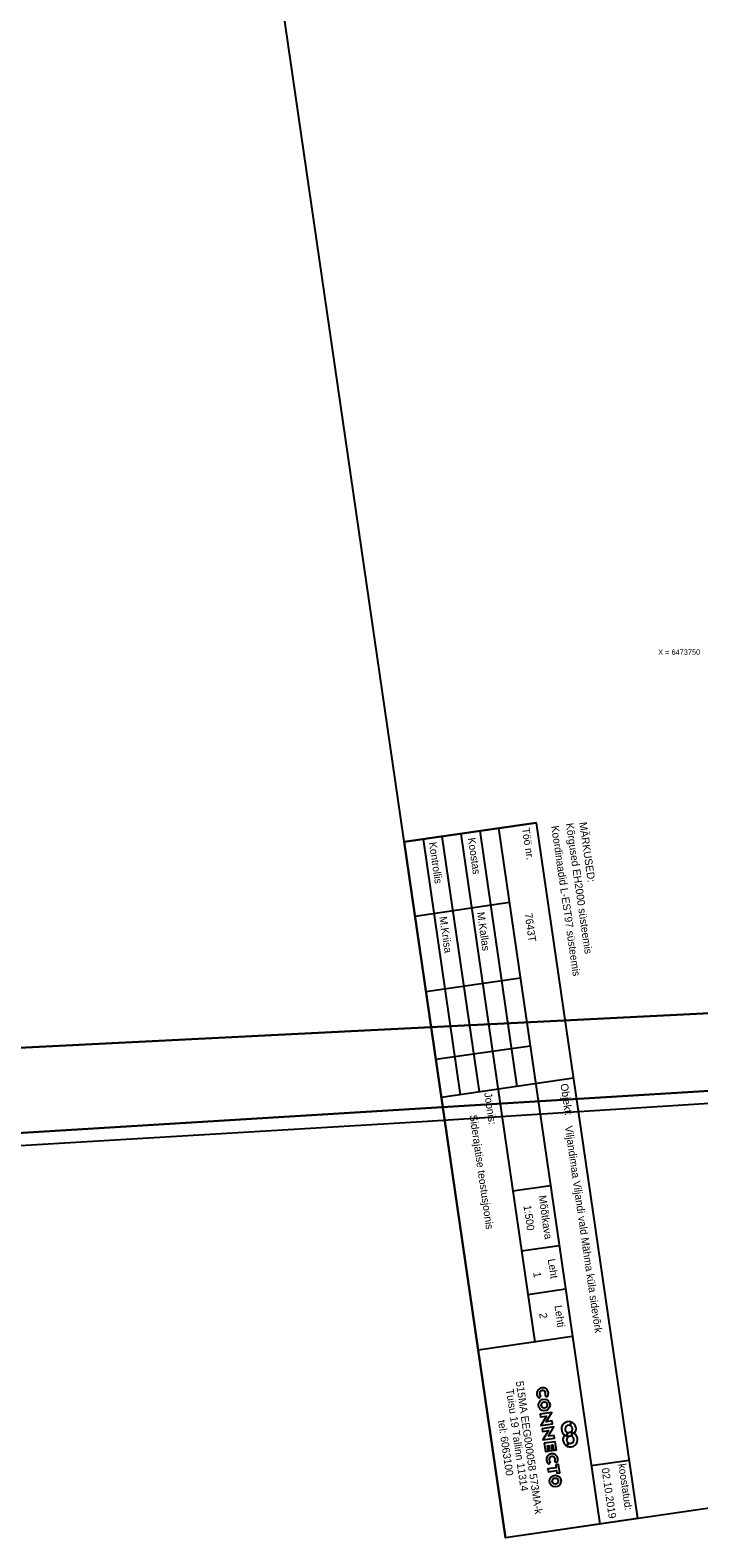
# Model space of a CAD drawing. Extents: x 604066 to 604956, y 6473634 to 6474346.
# Drawn here: x 604560.3 to 604648, y 6473633.8 to 6473831.5 of the extents above; entities that cross this region are included whole.
import ezdxf

# ---------------------------------------------------------------- set-up
doc = ezdxf.new("R2010")
doc.units = 0
for name, color, linetype in [('PIIR', 7, 'Continuous'), ('VORK', 7, 'Continuous'), ('VORMISTUS', 7, 'Continuous')]:
    doc.layers.add(name, color=color, linetype=linetype)

msp = doc.modelspace()

# ---------------------------------------------------------------- linework, layer by layer
at = {"layer": 'PIIR'}
msp.add_lwpolyline([(604392.23, 6473874.61), (604414.7, 6473872.41), (604426.55, 6473871.03), (604444.65, 6473869.66), (604482.63, 6473866.81), (604486.98, 6473866.41), (604549.55, 6473854.82), (604575.16, 6473852.02), (604645.55, 6473867.92), (604659, 6473875.69), (604714.62, 6473889.17), (604776, 6473903.81), (604824.84, 6473905.94), (604833.54, 6473909.5), (604821.94, 6473844.68), (604680.66, 6473747.8), (604687.73, 6473704.56), (604422.99, 6473691.29), (604421.99, 6473694.09), (604395.15, 6473723.9)], dxfattribs=at)
for points in [[(604429.15, 6473679), (604428.82, 6473685.17), (604422.99, 6473691.29), (604687.73, 6473704.56), (604689.38, 6473694.91)], [(604429.15, 6473679), (604689.38, 6473694.91), (604689.63, 6473693.43), (604663.03, 6473691.68), (604611.7, 6473688.38), (604559, 6473685.22), (604513.61, 6473682.6), (604464, 6473679.51), (604429.23, 6473677.5)]]:
    msp.add_lwpolyline(points, close=True, dxfattribs=at)
at = {"layer": 'VORMISTUS'}
for p, q in [((604626.65, 6473727.6), (604609.33, 6473725.08)), ((604626.65, 6473727.6), (604639.92, 6473636.37)), ((604614.28, 6473725.8), (604619.15, 6473692.3)), ((604616.75, 6473726.16), (604626.45, 6473659.51)), ((604619.23, 6473726.52), (604624.1, 6473693.03)), ((604621.7, 6473726.88), (604634.97, 6473635.65)), ((604609.33, 6473725.08), (604622.61, 6473633.85)), ((604611.81, 6473725.44), (604616.68, 6473691.94)), ((604623.12, 6473717.14), (604610.75, 6473715.33)), ((604624.56, 6473707.24), (604612.19, 6473705.43)), ((604625.85, 6473698.33), (604613.48, 6473696.54)), ((604631.52, 6473694.1), (604614.21, 6473691.58)), ((604628.5, 6473680), (604623.57, 6473679.28)), ((604629.66, 6473672.14), (604624.72, 6473671.42)), ((604630.49, 6473666.43), (604625.55, 6473665.71)), ((604631.4, 6473660.23), (604619.04, 6473658.43)), ((604628.09, 6473652.3), (604627.8, 6473652.52)), ((604631.25, 6473649.03), (604631.07, 6473648.59)), ((604631.25, 6473649.03), (604631.25, 6473649.03)), ((604630.75, 6473647.18), (604630.67, 6473647.71)), ((604630.67, 6473647.71), (604630.75, 6473647.18)), ((604631.26, 6473647.66), (604631.34, 6473647.13)), ((604631.34, 6473647.13), (604631.26, 6473647.66)), ((604630.83, 6473646.31), (604630.71, 6473645.83)), ((604630.71, 6473645.83), (604630.83, 6473646.31)), ((604629.34, 6473643.66), (604629.05, 6473643.88)), ((604638.81, 6473643.99), (604633.86, 6473643.27)), ((604639.92, 6473636.37), (604622.61, 6473633.84))]:
    msp.add_line(p, q, dxfattribs=at)
for points in [[(604563.86, 6474037.6), (604705.86, 6474058.26), (604764.62, 6473654.52), (604622.61, 6473633.85)], [(604622.61, 6473633.85), (604609.33, 6473725.08), (604626.65, 6473727.6), (604639.92, 6473636.37)], [(604628.73, 6473649.18), (604627.95, 6473649.06), (604628.69, 6473650.28), (604627.14, 6473650.05), (604627.19, 6473649.69), (604627.97, 6473649.8), (604627.23, 6473648.59), (604628.78, 6473648.81)], [(604629.01, 6473647.28), (604628.23, 6473647.17), (604628.96, 6473648.38), (604627.41, 6473648.15), (604627.47, 6473647.79), (604628.24, 6473647.91), (604627.5, 6473646.69), (604629.06, 6473646.92)], [(604627.69, 6473646.24), (604627.85, 6473645.16), (604628.21, 6473645.21), (604628.1, 6473645.93), (604628.28, 6473645.96), (604628.39, 6473645.24), (604628.75, 6473645.29), (604628.64, 6473646.01), (604628.82, 6473646.04), (604628.93, 6473645.31), (604629.29, 6473645.37), (604629.13, 6473646.45)], [(604629.21, 6473643.4), (604629.26, 6473643.03), (604628.18, 6473642.88), (604628.23, 6473642.52), (604629.31, 6473642.67), (604629.36, 6473642.31), (604629.72, 6473642.36), (604629.56, 6473643.45)]]:
    msp.add_lwpolyline(points, close=True, dxfattribs=at)
for points in [[(604609.33, 6473725.08), (604622.61, 6473633.85)], [(604627.24, 6473652.44), (604627.02, 6473652.15), (604627.02, 6473652.15)], [(604631.07, 6473648.59), (604631.13, 6473648.75), (604631.25, 6473649.03)], [(604628.5, 6473643.8), (604628.28, 6473643.51), (604628.28, 6473643.51)]]:
    msp.add_lwpolyline(points, dxfattribs=at)
for centre, radius in [((604627.69, 6473651.26), 0.762), ((604627.69, 6473651.26), 0.399), ((604629.14, 6473641.29), 0.762), ((604629.14, 6473641.29), 0.399)]:
    msp.add_circle(centre, radius, dxfattribs=at)
for centre, radius, start, end in [((604627.48, 6473652.76), 0.762, 323.2791, 233.2791), ((604627.48, 6473652.76), 0.399, 323.0841, 233.4849), ((604630.9, 6473648.13), 0.962, 69.0365, 260.8215), ((604630.9, 6473648.13), 0.481, 69.9549, 241.4092), ((604630.9, 6473648.13), 0.481, 278.2791, 69.9549), ((604630.9, 6473648.13), 0.962, 319.6888, 69.0406), ((604631.11, 6473646.71), 0.962, 139.6888, 245.1189), ((604630.9, 6473648.13), 0.962, 236.8695, 278.2791), ((604631.11, 6473646.71), 0.481, 98.2791, 234.6428), ((604630.9, 6473648.13), 0.481, 241.4092, 278.2791), ((604631.11, 6473646.71), 0.962, 245.1189, 80.8215), ((604630.9, 6473648.13), 0.962, 260.8215, 278.2791), ((604631.11, 6473646.71), 0.481, 234.6428, 61.4092), ((604631.11, 6473646.71), 0.962, 56.8695, 98.2791), ((604631.11, 6473646.71), 0.962, 80.8215, 98.2791), ((604631.11, 6473646.71), 0.481, 61.4092, 98.2791), ((604628.73, 6473644.12), 0.762, 323.2791, 233.2791), ((604628.73, 6473644.12), 0.399, 323.0841, 233.4849)]:
    msp.add_arc(centre, radius, start, end, dxfattribs=at)

# ---------------------------------------------------------------- texts
at = {"layer": 'VORK'}
msp.add_text('X = 6473750', height=0.7, dxfattribs=at).set_placement((604642.63, 6473749.62))
at = {"layer": 'VORMISTUS'}
for s, height, rotation, p in [('Kõrgused EH2000 süsteemis', 1, 278.2738, (604630.53, 6473727.49)), ('MÄRKUSED:', 1, 278.2738, (604632.27, 6473727.62)), ('Koostas', 1, 278.2766, (604617.67, 6473725.57)), ('Töö nr.', 1, 278.2766, (604624.77, 6473726.87)), ('Koordinaadid L-EST97 süsteemis ', 1, 278.2738, (604628.6, 6473727.14)), (' Kontrollis', 0.9997, 278.2766, (604612.52, 6473725.37)), ('M.Kallas', 1, 278.2766, (604618.87, 6473715.83)), ('7643T', 1, 278.2766, (604625.12, 6473715.68)), ('M.Kriisa', 1, 278.2766, (604613.94, 6473715.25)), ('Joonis:', 1, 278.2766, (604619.83, 6473692.16)), ('Objekt:', 1, 278.2766, (604629.81, 6473693.34)), ('Siderajatise teostusjoonis', 0.9997, 278.2766, (604617.9, 6473689.24)), ('Viljandimaa Viljandi vald Mähma küla sidevõrk', 0.9997, 278.2766, (604630.39, 6473687.79)), ('Mõõtkava', 1, 278.2766, (604626.94, 6473678.68)), ('1:500', 1, 278.2766, (604624.97, 6473677.39)), ('Leht', 1, 278.2766, (604628.15, 6473670.36)), ('1', 1, 278.2766, (604626.24, 6473668.64)), ('Lehti', 1, 278.2766, (604629.03, 6473664.27)), ('2', 1, 278.2766, (604627.03, 6473663.27)), ('515MA EEG000058 573MA-k', 0.9997, 278.2766, (604623.96, 6473654.33)), ('Tuisu 19 Tallinn 11314', 0.9997, 278.2766, (604622.68, 6473653.3)), ('tel: 6063100', 0.9997, 278.2766, (604621.63, 6473649.21)), ('02.10.2019', 1, 278.2766, (604635.2, 6473642.94)), ('koostatud:', 1, 278.2766, (604637.4, 6473643.51))]:
    msp.add_text(s, height=height, rotation=rotation, dxfattribs=at).set_placement(p)

doc.saveas('drawing.dxf')
